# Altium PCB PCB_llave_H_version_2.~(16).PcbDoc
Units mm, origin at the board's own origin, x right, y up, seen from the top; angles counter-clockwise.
Board outline 98.1 x 71.5 mm, 2 copper layers (Top Layer, Bottom Layer); 62 components, 35 nets, 185 pads, 5 vias.
Unrouted connection lines stored in the file: 28.
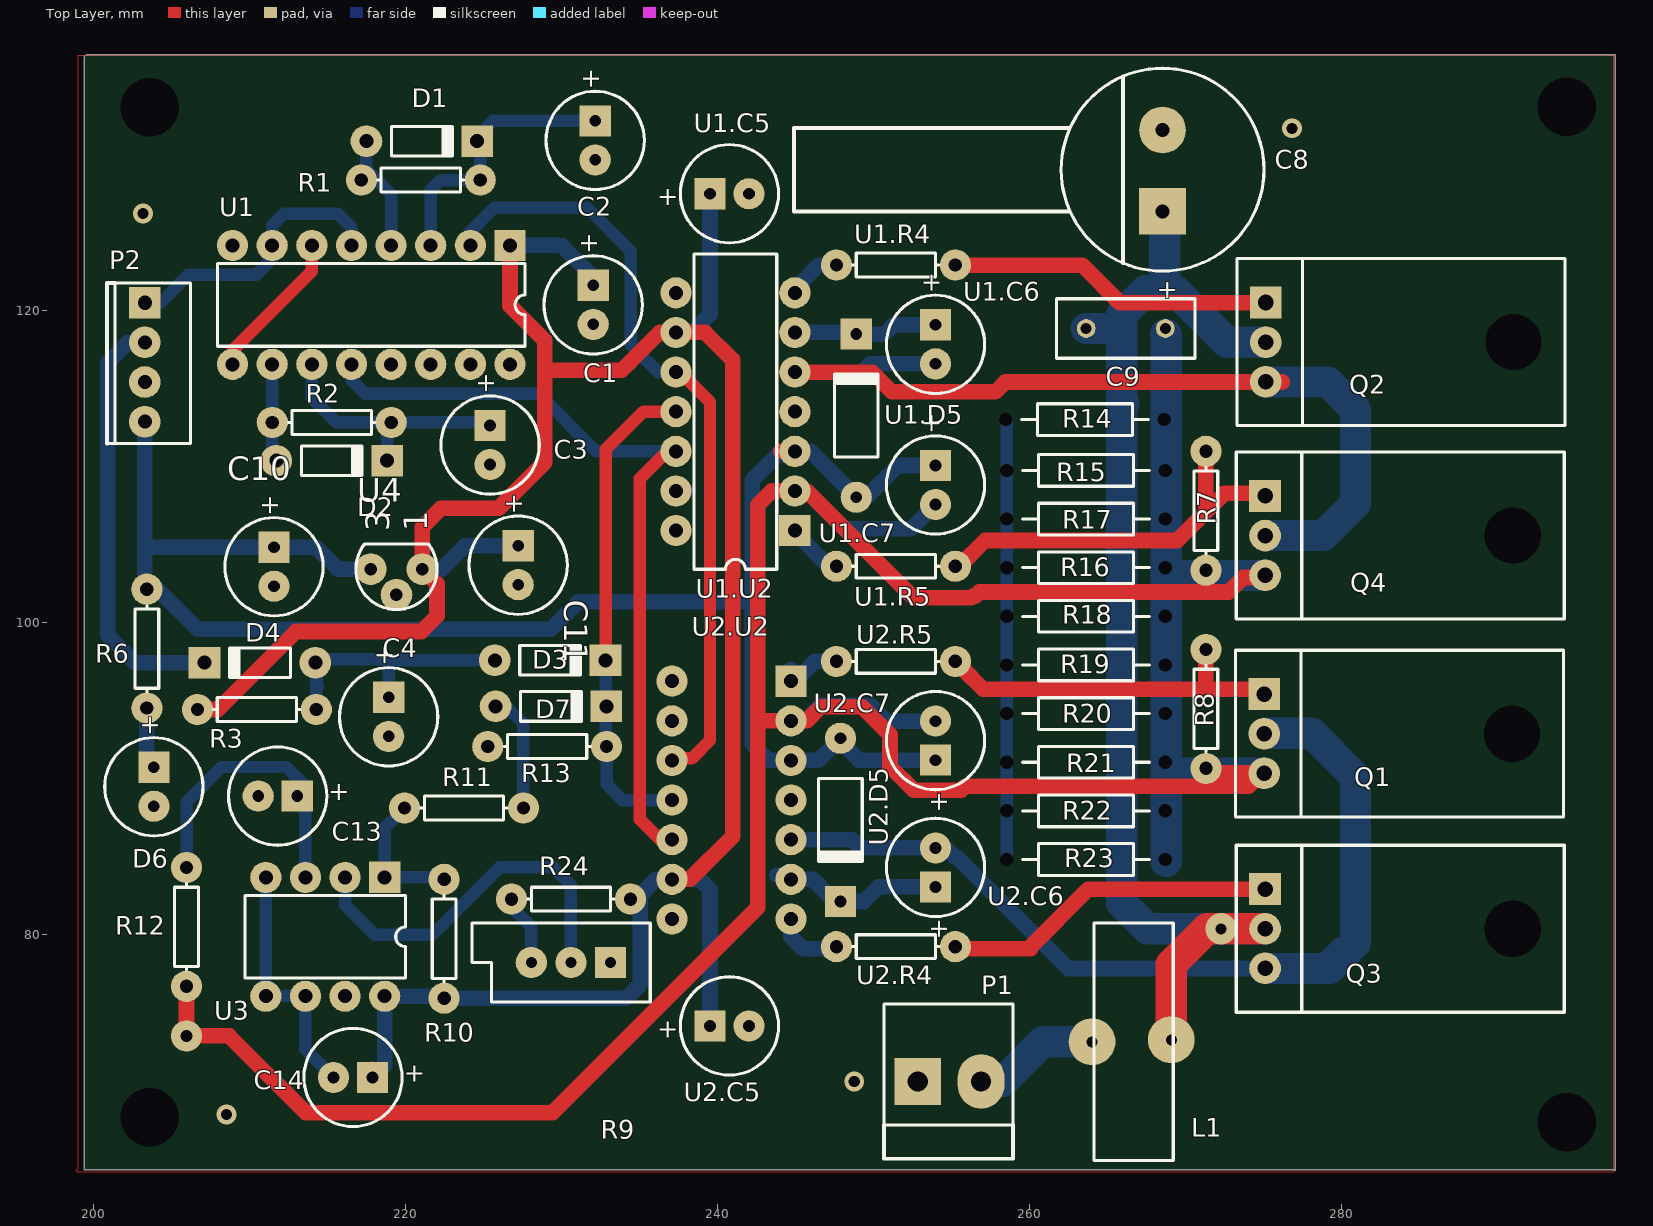
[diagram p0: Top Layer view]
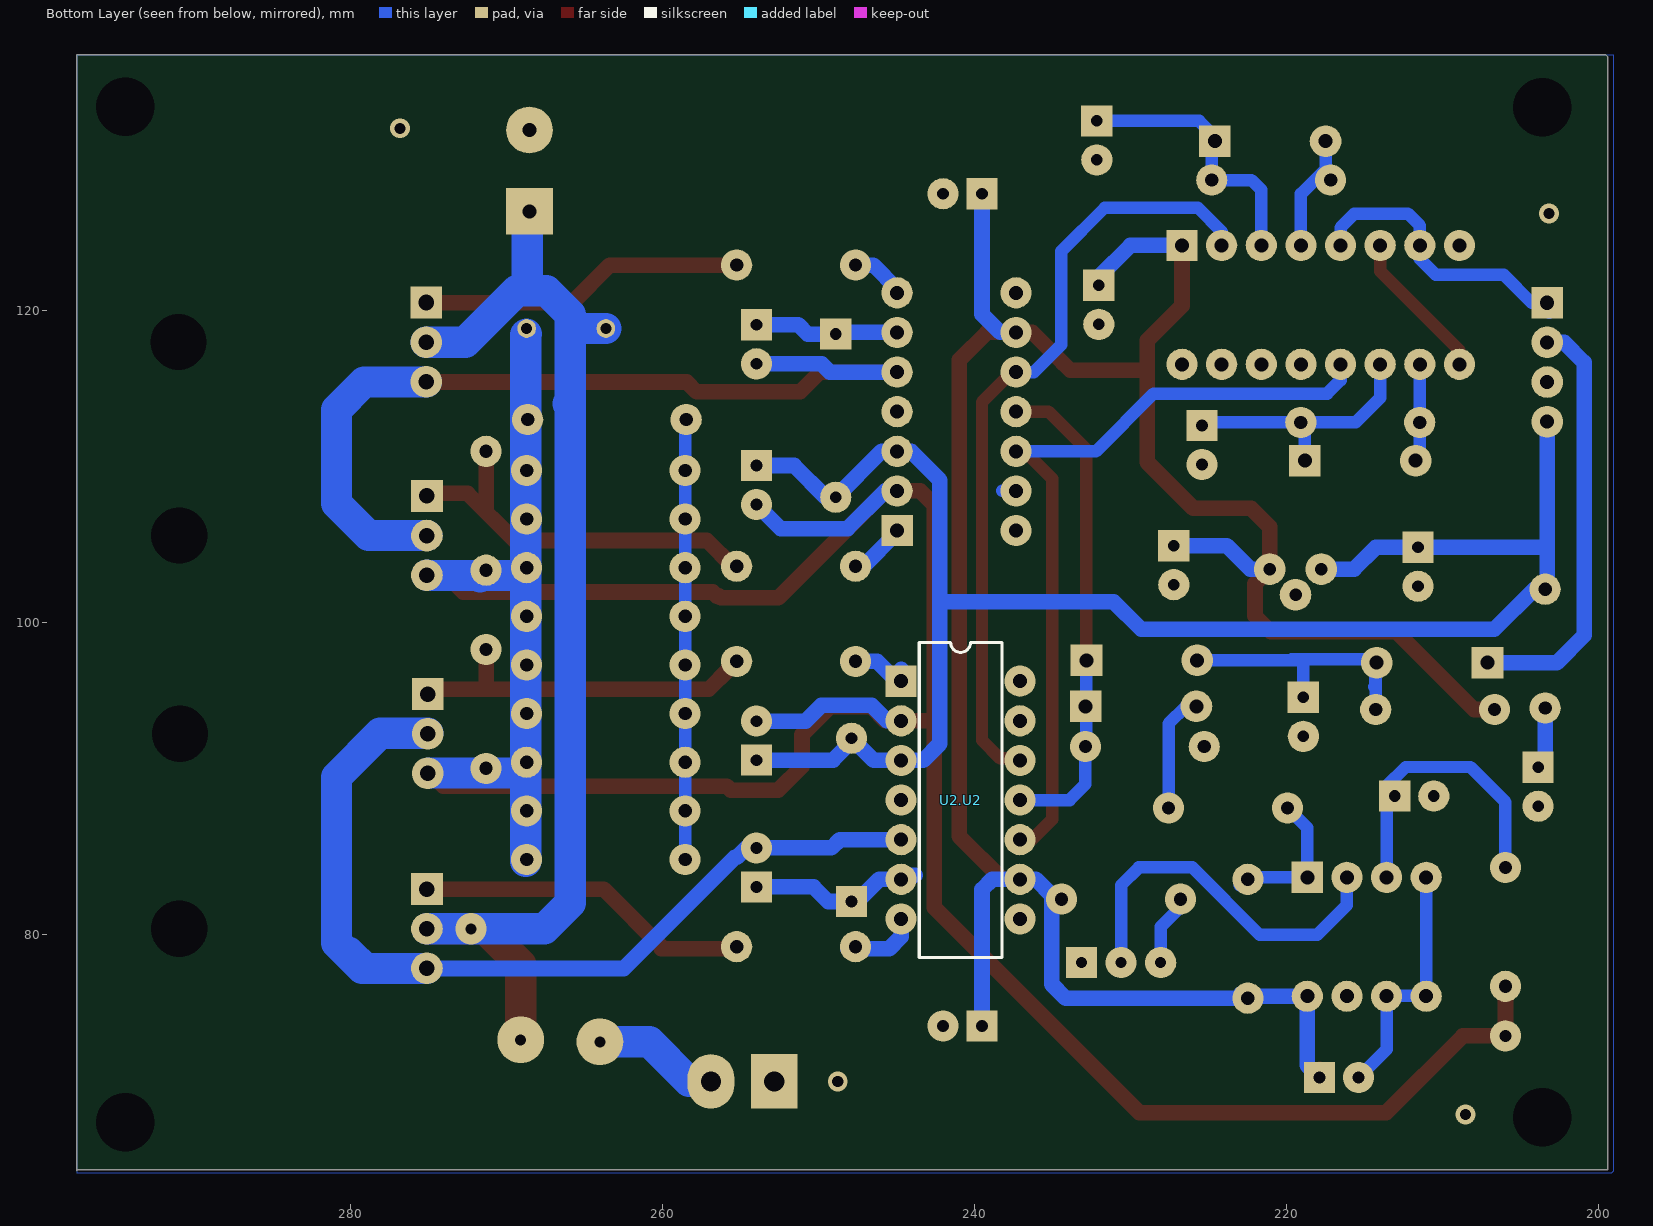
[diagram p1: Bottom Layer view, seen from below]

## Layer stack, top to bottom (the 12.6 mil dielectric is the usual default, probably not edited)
Top Layer: signal copper 0.0356
Dielectric: dielectric 0.32, FR-4, Dk 4.8
Bottom Layer: signal copper 0.0356

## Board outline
199.55,136.4 297.55,136.4 297.55,64.9 297.5,64.95 199.45,64.95 199.45,136.3

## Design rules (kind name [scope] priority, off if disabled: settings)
Clearance [All] p1: gap=0.4
ComponentClearance [All] p1: gap=0.254 collisioncheckmode=2 verticalgap=0.254
PlaneConnect [All] p1: planeconnectstyle=Direct reliefexpansion=0.508 reliefentries=4 reliefconductorwidth=0.254 reliefairgap=0.254
PolygonConnect [All] p1: connectstyle=Direct reliefconductorwidth=0.254 reliefentries=4 polygonreliefangle="90 Angle"
RoomDefinition U_regulador [InComponentClass('U_regulador')] p1: confinementstyle=ConfineIn formatcopy=TRUE lockcomponents=FALSE outline 206.7,98.85 231.45,98.85 231.45,109 206.7,109
RoomDefinition U2 [InComponentClass('U2')] p2: confinementstyle=ConfineIn formatcopy=TRUE lockcomponents=FALSE outline 276.86,69.723 229.616,69.723 229.616,109.474 276.86,109.474
RoomDefinition U1 [InComponentClass('U1')] p3: confinementstyle=ConfineIn formatcopy=TRUE lockcomponents=FALSE outline 271.272,133.604 230.759,133.604 230.759,101.981 271.272,101.981
RoomDefinition U_Puente_H [InComponentClass('U_Puente_H')] p4: confinementstyle=ConfineIn formatcopy=TRUE lockcomponents=FALSE outline 297.3,136.05 297.3,64.897 244.2,64.897 244.2,136.05
RoomDefinition U_INITShutdown [InComponentClass('U_INITShutdown')] p5: confinementstyle=ConfineIn formatcopy=TRUE lockcomponents=FALSE outline 199.45,106.045 199.45,90.297 236.347,90.297 236.347,106.045
RoomDefinition U_Shutdown [InComponentClass('U_Shutdown')] p6: confinementstyle=ConfineOut formatcopy=TRUE lockcomponents=FALSE outline 201.041,103.886 202.438,103.886 202.438,100.584 201.041,100.584
RoomDefinition Llave_H_esquema [InComponentClass('Llave_H_esquema')] p7: confinementstyle=ConfineIn formatcopy=TRUE lockcomponents=FALSE outline 199.4,64.897 297.55,64.897 297.55,136.398 199.4,136.398
RoomDefinition U_4049 [InComponentClass('U_4049')] p8: confinementstyle=ConfineIn formatcopy=TRUE lockcomponents=FALSE outline 206.15,105.4 240.186,105.4 240.186,135.88 206.15,135.88
RoutingVias [All] p1: holewidth=0.711 width=1.27 viastyle="Through Hole" minholewidth=0.711 minwidth=1.27 maxholewidth=0.711 maxwidth=1.27
SolderMaskExpansion [All] p1: expansion=0.102
TestPointUsage [All] p1: valid=0 allowmultiple=FALSE
Testpoint [All] p1: side=15 testpointundercomponent=TRUE minsize=1.016 maxsize=2.54 preferedsize=1.524 minholesize=0 maxholesize=1.016 preferedholesize=0.813 testpointgrid=0.025 style=1023 order=0123456789
Width [All] p1: maxlimit=3 minlimit=0.8 preferedwidth=1
17 further rules are at their usual default settings.

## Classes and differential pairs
component class Llave_H_esquema: D6 P1 P2 R6
component class U_4049: C1 C2 C3 D1 D2 R1 R2 U1
component class U_Puente_H: C8 C9 L1 Q1 Q2 Q3 Q4 R7 R8
component class U_Shutdown: C13 C14 D7 R9 R10 R11 R12 R13 R14 R15 R16 R17 R18 R19 R20 R21 R22 R23 R24 U3
channel class IR2110: U1 U2
component class U_INITShutdown: C4 D3 D4 R3
component class U1: U1.C5 U1.C6 U1.C7 U1.D5 U1.R4 U1.R5 U1.U2 U_1_C5 U_1_C6 U_1_C7 U_1_D5 U_1_R4 U_1_R5 U_1_U2
component class U2: D5 U2.C5 U2.C6 U2.C7 U2.D5 U2.R4 U2.R5 U2.U2 U_2.D5 U_2_C5 U_2_C6 U_2_C7 U_2_R4 U_2_R5 U_2_U2
component class U_regulador: C10 C11 U4

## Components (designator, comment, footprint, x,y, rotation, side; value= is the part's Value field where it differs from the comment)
C1 "Cap Pol1 0.1u" CAPPR2.5-6.3X5 232.058,120.386 r270 top
C2 "Cap Pol1" CAPPR2.5-6.3X5 232.185,130.927 r270 top
C3 "Cap Pol1" CAPPR2.5-6.3X5 225.45,111.4 r270 top
C4 "Cap Pol1 4.7u" CAPPR2.5-6.3X5 218.948,93.98 r270 top
C8 "Cap Pol1" CAPPR5-13X16 268.55,129.05 r0 top
C9 "Cap" RAD-0.2 266.192,118.872 r180 top
C10 "Cap Pol1 0.1u" CAPPR2.5-6.3X5 211.6,103.6 r270 top
C11 "Cap Pol1 0.1u" CAPPR2.5-6.3X5 227.25,103.7 r270 top
C13 "Cap Pol1 4.7u" CAPPR2.5-6.3X5 211.836,88.9 r180 top
C14 "Cap Pol1 0.1u" CAPPR2.5-6.3X5 216.662,70.866 r180 top
D1 "Diode1" DO-35 221.075,130.877 r0 top
D2 "Diode1" DO-35 215.3,110.4 r0 top
D3 "Diode1" DO-35 229.3,97.6 r0 top
D4 "Diode1" DO-35 210.7,97.45 r180 top
D6 "LED0" CAPPR2.5-6.3X5 203.9,89.5 r270 top
D7 "Diode1" DO-35 229.35,94.65 r0 top
L1 "Inductor" BOBINA_CHOQUE 264.16,75.692 r270 top
P1 "Header 2" PWHEADER1X2 255.016,70.612 r0 top
P2 "Header 4" HDR1X5 195.7,112.9 r270 top
Q1 "IRF3205" TO_220_H 284.9,82.05 r270 top
Q2 "IRF3205" TO_220_H 284.95,119.65 r270 top
Q3 "IRF3205" TO_220_H 284.85,94.55 r270 top
Q4 "IRF3205" TO_220_H 284.9,107.25 r270 top
R1 "18k" AXIAL-0.3 221.009,128.387 r180 top
R2 "18k" AXIAL-0.3 215.3,112.85 r0 top
R3 "4.7k" AXIAL-0.3 210.5,94.45 r180 top
R6 "1.2k" AXIAL-0.3 203.45,98.35 r90 top
R7 "6.8" AXIAL-0.3 271.33,107.188 r90 top
R8 "6.8" AXIAL-0.3 271.33,94.488 r90 top
R9 "RPot" VR5 230.632,78.232 r180 top
R10 "3.3k" AXIAL-0.3 222.504,79.756 r270 top
R11 "470" AXIAL-0.3 223.774,88.138 r0 top
R12 "6.8" AXIAL-0.3 205.994,80.518 r90 top locked
R13 "10k" AXIAL-0.3 229.108,92.075 r0 top
R14 "Res2" AXIAL-0.4 263.585,113.03 r0 top
R15 "Res2" AXIAL-0.4 263.652,109.774 r0 top
R16 "Res2" AXIAL-0.4 263.652,106.657 r0 top
R17 "Res2" AXIAL-0.4 263.652,103.539 r0 top
R18 "Res2" AXIAL-0.4 263.652,100.422 r0 top
R19 "Res2" AXIAL-0.4 263.652,97.305 r0 top
R20 "Res2" AXIAL-0.4 263.652,94.188 r0 top
R21 "Res2" AXIAL-0.4 263.652,91.07 r0 top
R22 "Res2" AXIAL-0.4 263.652,87.953 r0 top
R23 "Res2" AXIAL-0.4 263.652,84.836 r0 top
R24 "6.8" AXIAL-0.3 230.632,82.296 r0 top
U1 "MC54HC4049J" 620-09 217.834,120.386 r180 top
U1.C5 "Cap Pol1 4.7u" CAPPR2.5-6.3X5 240.792,127.508 r0 top (schematic designator C5)
U1.C6 "Cap Pol1" CAPPR2.5-6.3X5 254,117.856 r270 top (schematic designator C6)
U1.C7 "Cap Pol1" CAPPR2.5-6.3X5 254,108.839 r270 top (schematic designator C7)
U1.D5 "Diode" DO-204AL 248.92,113.284 r90 top (schematic designator D5)
U1.R4 "10" AXIAL-0.3 251.46,122.936 r0 top (schematic designator R4)
U1.R5 "10" AXIAL-0.3 251.46,103.632 r0 top (schematic designator R5)
U1.U2 "IR2110" PDIP14 241.173,113.538 r90 top (schematic designator U2)
U2.C5 "Cap Pol1 4.7u" CAPPR2.5-6.3X5 240.792,74.168 r0 top (schematic designator C5)
U2.C6 "Cap Pol1" CAPPR2.5-6.3X5 254,84.328 r90 top (schematic designator C6)
U2.C7 "Cap Pol1" CAPPR2.5-6.3X5 254,92.456 r90 top (schematic designator C7)
U2.D5 "Diode" DO-204AL 247.904,87.376 r270 top (schematic designator D5)
U2.R4 "10" AXIAL-0.3 251.46,79.248 r0 top (schematic designator R4)
U2.R5 "10" AXIAL-0.3 251.46,97.536 r0 top (schematic designator R5)
U2.U2 "IR2110" PDIP14 240.919,88.646 r270 bottom (schematic designator U2)
U3 "LM393N" 626-05 214.884,79.883 r180 top
U4 "µA78L05ACLP" LP03 219.45,103.45 r90 top

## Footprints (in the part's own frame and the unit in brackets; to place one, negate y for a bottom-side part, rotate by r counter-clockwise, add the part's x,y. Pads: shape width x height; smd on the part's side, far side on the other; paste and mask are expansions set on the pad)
620-09 [mm] "DIP; 16 Leads; Row Spacing 7.62 mm; Pitch 2.54 mm"
  rect 2x2 hole 0.9: 1(-8.89,-3.81)
  round 2 hole 0.9: 2(-6.35,-3.81) 3(-3.81,-3.81) 4(-1.27,-3.81) 5(1.27,-3.81) 6(3.81,-3.81) 7(6.35,-3.81) 8(8.89,-3.81) 9(8.89,3.81) 10(6.35,3.81) 11(3.81,3.81) 12(1.27,3.81) 13(-1.27,3.81) 14(-3.81,3.81) 15(-6.35,3.81) 16(-8.89,3.81)
  silkscreen extent -9.85,-2.65 9.85,2.65
626-05 [mm] "DIP; 8 Leads; Row Spacing 7.62 mm; Pitch 2.54 mm"
  rect 2x2 hole 0.9: 1(-3.81,-3.81)
  round 2 hole 0.9: 2(-1.27,-3.81) 3(1.27,-3.81) 4(3.81,-3.81) 5(3.81,3.81) 6(1.27,3.81) 7(-1.27,3.81) 8(-3.81,3.81)
  silkscreen extent -5.15,-2.65 5.15,2.65
AXIAL-0.3 [mm] "Resistor; 2 Leads"
  round 2 hole 0.85: 1(-3.81,0) 2(3.81,0)
  silkscreen extent -2.77,-0.76 2.77,0.76
AXIAL-0.4 [mm] "Resistor; 2 Leads"
  round 0 / inner round 0 / far side round 2 hole 0.85: 1(-5.08,0) 2(5.08,0)
  silkscreen extent -4.06,-1.02 4.06,1.02
BOBINA_CHOQUE [mm]
  round 3 hole 0.7: 1(2.54,-0.127) 2(2.413,4.953)
  silkscreen extent -5.08,0 10.16,5.08
CAPPR2.5-6.3X5 [mm] "Capacitor, Electrolytic, Radial; Body 6.3 x 5 mm (Dia.xH typ); Pin Spacing 2.5 mm (typ)"
  rect 2x2 hole 0.75: 1(-1.25,0)
  round 2 hole 0.75: 2(1.25,0)
  silkscreen extent -3.15,-3.15 3.15,3.15
CAPPR5-13X16 [mm] "Capacitor, Electrolytic, Radial; Body 13 x 16 mm (Dia.xH typ); Pin Spacing 5 mm (typ)"
  rect 3x3 hole 0.9: 1(0,-2.667)
  round 3 hole 0.9: 2(0,2.54)
  silkscreen extent -23.62,-6.5 6.5,6.5
DO-35 [mm] "Diode, Axial; Body 3.8 x 1.9 mm (LxDia. max), Lead Dia. 0.53 mm (max)"
  round 2.032 hole 0.9: 1(-3.55,0)
  rect 2.032x2.032 hole 0.9: 2(3.55,0)
  silkscreen extent -1.95,-0.95 2.05,0.95
DO-204AL [mm] "Diode, Axial; Body 5.2 x 2.7 mm (LxDia. max), Lead Dia. 0.86 mm (max)"
  round 2 hole 0.75: 1(-5.23,0)
  rect 2x2 hole 0.75: 2(5.23,0)
  silkscreen extent -2.65,-1.41 2.75,1.4
HDR1X5 [mil]
  rect 80x80 hole 35.43: 1(-300,300)
  round 80 / inner round 0 / far side round 80 hole 35.43: 2(-200,300) 3(-100,300) 4(0,300)
  silkscreen extent -350,205 55,415
LP03 [mil] "TO, Flat Index; 3 In-Line, Axial Leads; Body Dia. 4.8mm; Leads 0.56 x 0.41 mm (max)"
  round 80 hole 31.5: 1(0,-65) 2(-65,0) 3(0,65)
  silkscreen extent -102,-102 63,102
PDIP14 [mm] "DIP; 14 Leads; Row Spacing 7.62 mm; Pitch 2.54 mm"
  rect 2x2 hole 0.9: 1(-7.62,-3.81)
  round 2 hole 0.9: 2(-5.08,-3.81) 3(-2.54,-3.81) 4(0,-3.81) 5(2.54,-3.81) 6(5.08,-3.81) 7(7.62,-3.81) 8(7.62,3.81) 9(5.08,3.81) 10(2.54,3.81) 11(0,3.81) 12(-2.54,3.81) 13(-5.08,3.81) 14(-7.62,3.81)
  silkscreen extent -10.1,-2.65 10.1,2.65
PWHEADER1X2 [mm]
  rect 3x3 / inner round 0 / far side rect 3x3.5 hole 1.3: 1(-2.159,0)
  oval 3x3.5 / inner round 0 / far side oval 3x3.5 hole 1.3: 2(1.905,0)
  silkscreen extent -4.32,-4.95 3.94,4.95
RAD-0.2 [mm] "Jumper Wire; 2 Leads"
  round 1.2 hole 0.7: 1(-2.54,0) 2(2.54,0)
  silkscreen extent -4.44,-1.91 4.44,1.91
TO_220_H [mil] "to-220 horizontal"
  rect 80x80 hole 39.37: 1(-35,-385)
  round 80 hole 39.37: 2(65,-385) 3(165,-385)
  round 80 hole 141.73: 4(65,240)
  silkscreen extent -146,-458 276,370
VR5 [mm] "Potentiometer; 3 Leads"
  rect 2x2 hole 0.7: 1(-2.54,0)
  round 2 hole 0.7: 2(2.54,0) 3(0,0)
  silkscreen extent -5.08,-2.54 6.35,2.54

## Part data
C1 C4 C10 C11 C14 U1.C5 U2.C5: library part "Cap Pol1", "Polarized Capacitor (Radial)"
C2 C3 C8 U1.C6 U1.C7 U2.C6 U2.C7: "Polarized Capacitor (Radial)"
C9: "Capacitor"
C13: library part "Cap Pol1", "Polarized 16V"
D1 D2 D3 D4 D7: library part Diode, "1N4148"
D6: "Typical INFRARED GaAs LED"
P1: "Header, 2-Pin"
P2: "Header, 4-Pin"
Q1 Q2 Q3 Q4: "HEXFET Power MOSFET"
R1 R2 R3 R6 R7 R8 R10 R11 R12 R13 R24 U1.R4 U1.R5 U2.R4 U2.R5: library part Res2, "Resistor"
R9: "Potenciomentro multivuelta"
R14 R15 R16 R17 R18 R19 R20 R21 R22 R23: "metal film 1W"
U1: "Hex Inverting Buffer/Logic-Level Down Converter"
U1.D5 U2.D5: "1N5819"
U1.U2 U2.U2: "High and Low Side Driver"
U3: "Dual Comparator"
U4: "Positive-Voltage Regulator"

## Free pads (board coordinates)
  round 1.524 hole 3.75: 0(203.65,68.3) 0(203.65,133.05) 0(294.45,68) 0(294.45,133.096)
  round 2 hole 0.762: 1(205.994,73.533)

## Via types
v1: diameter 1.27, hole 0.711, Top Layer to Bottom Layer, 4 vias
v2: diameter 2, hole 0.711, Top Layer to Bottom Layer, 1 vias

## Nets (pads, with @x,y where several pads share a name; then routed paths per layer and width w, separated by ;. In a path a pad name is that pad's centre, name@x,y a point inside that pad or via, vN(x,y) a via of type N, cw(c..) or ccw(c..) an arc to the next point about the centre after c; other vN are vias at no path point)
COMMON: C9.1 pad.1 Q3.3 Q4.3 R7.1 R8.1 R12.1 R14.2 R15.2 R16.2 R17.2 R18.2 R19.2 R20.2 R21.2 R22.2 R23.2 U1.C7.2 U1.U2.2 U2.C7.2 U2.U2.2 | length 214.8
  Top Layer w1: pad.1 208.717,73.533 213.65,68.6 229.45,68.6 242.6,81.75 242.6,107.55 243.508,108.458 U1.U2.2 ; pad.1@205.994,73.556 R12.1 ; 242.6,93.726 245.745,93.726 246.634,94.615 249.301,94.615 251.079,92.837 251.079,90.805 252.603,89.281 255.646,89.281 255.9,89.535 274.066,89.535 Q3.3@274.913,90.382 ; U1.U2.2@245.745,108.458 252.603,101.6 256.286,101.6 256.413,101.727 256.54,101.727 256.794,101.981 272.796,101.981 273.727,102.912 Q4.3@275.121,102.912 ; R8.1@271.78,90.382 Q3.3@275.071,90.382
  Bottom Layer w1: U1.U2.2 245.745,108.458 248.158,106.045 252.456,106.045 U1.C7.2 ; U2.U2.2@245.633,93.726 246.629,94.722 249.829,94.722 250.845,93.706 U2.C7.2 ; R7.1@271.713,102.997 R7.1@271.798,102.912
  Bottom Layer w2: C9.1@268.732,118.526 268.792,118.465 R23.2@268.792,84.709 ; R21.2@268.792,90.382 Q3.3@275,90.382 ; R17.2@268.792,103.031 Q4.3 ; R7.1@271.713,102.965 R7.1@271.78,103.031
GND: C1.2 C2.2 C3.2 C4.2 C8.2 C10.2 C11.2 C13.2 C14.2 D6.2 P1.1 P2.3 pad.0 R9.1 R13.1 R14.1 R15.1 R16.1 R17.1 R18.1 R19.1 R20.1 R21.1 R22.1 R23.1 U1.8 U1.C5.2 U1.U2.13 U2.C5.2 U2.U2.13 U3.4 U3.5 U3.6 U4.2 | length 45.2
  Top Layer w0.8: U3.5 211.094,76.093 U3.5@211.074,76.113 ; U3.6@213.594,76.093 U3.6
  Bottom Layer w0.8: U3.5 U3.4 ; U3.5@211.094,76.093 U3.6@213.594,76.093 ; U3.6 213.614,72.664 C14.2 ; U1.U2.13 U1.U2.13@238.252,108.458 ; R23.1 R14.1@258.572,112.963
  other v1: 208.55,68.5 248.793,70.612 203.2,126.238 276.85,131.7
HO1: Q2.1 U1.R4.2 | length 20.9
  Top Layer w1: U1.R4.2 263.398,122.936 265.811,120.523 Q2.1@275.171,120.523
HO2: Q1.1 U2.R4.2 | length 20.9
  Top Layer w1: U2.R4.2@255.905,79.121 260.096,79.121 ; 259.969,79.121 263.779,82.931 Q1.1@275.121,82.931
IN_SD: D4.2 P2.2 | length 27.3
  Bottom Layer w1: P2.2 202.23,117.98 200.95,116.7 200.95,99.2 202.7,97.45 D4.2
LO1: Q4.1 R7.2 U1.R5.2 | length 26
  Top Layer w1: U1.R5.2 255.524,103.632 257.175,105.283 269.494,105.283 272.511,108.3 274.813,108.3 Q4.1@275.121,107.992 ; 271.33,107.119 R7.2 ; R7.2@271.78,110.998 R7.2@271.78,111.252
LO2: Q3.1 R8.2 U2.R5.2 | length 23.2
  Top Layer w1: U2.R5.2@255.778,97.536 255.778,97.028 257.048,95.758 Q3.1@275,95.758 ; 271.3,95.758 271.33,95.788 R8.2 ; R8.2@271.526,98.679 R8.2@271.78,98.425
MOTOR+: Q2.3 Q4.2 U1.C6.2 U1.U2.5 | length 60.4
  Top Layer w1: U1.U2.5 249.936,116.078 251.206,114.808 257.836,114.808 258.471,115.443 276.225,115.443
  Bottom Layer w1: U1.U2.5 249.301,116.078 249.829,116.606 U1.C6.2
  Bottom Layer w2: Q4.2 278.873,105.599 280.924,107.65 280.924,113.665 279.146,115.443 Q2.3@275.171,115.443
MOTOR-: Q1.3 Q3.2 U2.C6.2 U2.U2.5 | length 62.3
  Bottom Layer w1: U2.U2.5 248.666,86.106 249.194,85.578 254.655,85.578 255.255,84.978 255.382,84.978 262.509,77.851 Q1.3@275.121,77.851
  Bottom Layer w2: Q3.2@275.071,92.922 278.13,92.922 280.924,90.128 280.924,79.502 279.273,77.851 276.225,77.851 ; Q1.3 279.109,77.859 280.15,78.9
NetC2_1: C2.1 D1.2 R1.1 U1.3 | length 18.1
  Bottom Layer w0.8: U1.3 221.644,127.752 222.279,128.387 R1.1@225.2,128.387 ; R1.1@224.825,128.387 224.825,131.377 225.625,132.177 C2.1
NetC3_1: C3.1 D2.2 R2.2 U1.11 | length 22
  Bottom Layer w0.8: U1.11 214.024,114.426 215.6,112.85 C3.1@225.25,112.85 ; D2.2@218.844,110.4 R2.2@218.844,111.977 ; R2.2 C3.1@225.25,112.85 ; C3.1 C3.1@225.25,112.85
NetC4_1: C4.1 D3.1 D4.1 R3.1 | length 20.3
  Bottom Layer w0.8: R3.1 214.31,97.66 219.69,97.66 219.75,97.6 ; D4.1@214.35,97.66 214.35,95.96 214.41,95.9 ; C4.1 218.948,97.598 ; 218.95,97.6 D3.1 D3.1@225.306,98.044
NetC13_1: C13.1 R12.2 U3.3 | length 19.1
  Bottom Layer w0.8: R12.2 205.994,88.519 208.24,90.765 212.384,90.765 213.614,89.535 U3.3
NetD1_1: D1.1 R1.2 U1.4 | length 7.3
  Bottom Layer w0.8: D1.1 217.525,129.077 219.104,127.498 U1.4
NetD2_1: D2.1 R2.1 U1.10 | length 6.3
  Bottom Layer w0.8: U1.10 211.484,110.666 D2.1
NetD6_1: D6.1 R6.1 | length 4
  Bottom Layer w1: R6.1 203.45,91.2 D6.1
NetD7_1: D7.1 R11.2 | length 7.7
  Bottom Layer w0.8: D7.1 226.484,94.65 227.584,93.55 R11.2
NetR9_2: R9.2 R24.1 | length 4.8
  Bottom Layer w0.8: R24.1@226.949,82.55 226.949,81.661 228.092,80.518 R9.2
NetR9_3: R9.3 U3.2 | length 24.3
  Bottom Layer w0.8: U3.2 216.154,81.915 218.059,80.01 221.742,80.01 226.06,84.328 229.489,84.328 230.632,83.185 R9.3
NetR10_1: R10.1 R11.1 U3.1 | length 9.5
  Bottom Layer w0.8: R11.1 218.694,86.868 U3.1 222.504,83.693 R10.1@223.012,83.185
NetU1.C6_1: U1.C6.1 U1.D5.2 U1.U2.6 | length 9.8
  Bottom Layer w1: U1.U2.6 248.308,118.618 248.412,118.514 250.721,118.514 251.313,119.106 U1.C6.1 ; U1.D5.2@248.943,118.872 U1.D5.2@249.301,118.514
NetU1.R4_1: U1.R4.1 U1.U2.7 | length 3.8
  Bottom Layer w1: U1.U2.7 244.983,121.412 246.507,122.936 U1.R4.1@247.904,122.936
NetU1.R5_1: U1.R5.1 U1.U2.1 | length 3.7
  Bottom Layer w1: U1.U2.1 244.983,105.791 247.142,103.632 U1.R5.1
NetU1_6: U1.6 U1.9 | length 9.9
  Top Layer w0.8: U1.9 208.944,117.465 214.024,122.545 U1.6
  Bottom Layer w0.8: U1.9 U1.9@208.944,116.703
NetU2.C6_1: U2.C6.1 U2.D5.2 U2.U2.6 | length 10.8
  Bottom Layer w1: U2.U2.6@243.84,83.82 U2.U2.6@244.602,83.82 ; U2.U2.6 246.126,83.566 U2.D5.2@247.673,82.019 ; U2.D5.2 249.405,82.146 250.337,83.078 U2.C6.1
NetU2.R4_1: U2.R4.1 U2.U2.7 | length 4.9
  Bottom Layer w1: U2.U2.7 244.729,79.883 245.491,79.121 U2.R4.1@248.158,79.121
NetU2.R5_1: U2.R5.1 U2.U2.1 | length 4.7
  Bottom Layer w1: U2.U2.1@244.729,97.028 U2.U2.1 244.983,96.266 246.253,97.536 U2.R5.1@248.158,97.536
PWM: P2.1 U1.5 U1.7 | length 18.9
  Bottom Layer w0.8: P2.1@203.2,119.888 P2.1@203.576,120.264 ; P2.1 204.319,120.52 206.1,122.301 210.45,122.301 211.484,123.335 211.484,125.466 212.246,126.228 215.675,126.228 216.564,125.339 U1.5
SD: D3.2 D7.2 R13.2 U1.U2.11 U2.U2.11 | length 31.6
  Top Layer w0.8: D3.2 232.85,111.1 235.288,113.538 U1.U2.11
  Bottom Layer w0.8: D3.2 232.85,92.068 232.918,92 232.918,89.662 233.934,88.646 U2.U2.11
U1.HIN: U1.2 U1.U2.10 U2.U2.12 | length 50
  Top Layer w0.8: U2.U2.12@237.236,91.313 238.379,91.313 239.545,92.479 239.545,114.155 237.622,116.078 U1.U2.10
  Bottom Layer w0.8: U1.2 224.184,125.085 225.708,126.609 231.677,126.609 234.471,123.815 234.471,117.827 236.22,116.078 U1.U2.10
U1.LIN: U1.12 U1.U2.12 U2.U2.10 | length 51.2
  Top Layer w0.8: U2.U2.10 236.344,86.106 235.05,87.4 235.05,109.25 236.798,110.998 U1.U2.12
  Bottom Layer w0.8: U1.12 216.564,115.56 217.424,114.7 228.55,114.7 232.252,110.998 U1.U2.12
VCC: C10.1 P2.4 R6.2 U1.C7.1 U1.D5.1 U1.U2.3 U2.C7.1 U2.D5.1 U2.U2.3 U4.3 | length 112.3
  Top Layer w1: U1.U2.3@244.098,110.998 U1.U2.3
  Bottom Layer w1: 203.32,104.75 203.42,104.85 214.3,104.85 215.7,103.45 U4.3 ; P2.4 203.32,102.29 R6.2 204.14,102.16 206.7,99.6 229.35,99.6 231.1,101.35 242.2,101.35 242.25,101.3 ; U2.C7.1 249.094,91.206 247.904,92.396 U2.D5.1 246.484,91.186 243.314,91.186 242.25,92.25 242.25,109.15 244.098,110.998 245.976,110.998 U1.D5.1 249.554,108.054 251.589,110.089 U1.C7.1
VCC_MOTOR: L1.1 P1.2 | length 8.2
  Bottom Layer w2: P1.2 258.318,70.612 260.858,73.152 L1.1
VCC_MOTOR_FILTRADO: C8.1 C9.2 L1.2 Q1.2 Q2.2 | length 78
  Top Layer w2: L1.2 269.113,78.105 271.399,80.391 Q1.2@275.121,80.391
  Bottom Layer w2: C9.2 265.811,118.872 265.938,118.745 ; 265.938,113.919 266.065,114.046 ; 268.692,121.579 C8.1@268.692,126.45 ; Q1.2@275.121,80.391 267.589,80.391 265.938,82.042 265.938,119.761 267.462,121.285 269.367,121.285 272.669,117.983 Q2.2@275.171,117.983
  other v2: 272.288,80.391
VDD: C1.1 C11.1 C14.1 R3.2 R10.2 R24.2 U1.1 U1.C5.1 U1.U2.9 U2.C5.1 U2.U2.9 U3.8 U4.1 | length 164
  Top Layer w0.8: C14.1 C14.1@217.912,71.481 ; U3.8@218.567,76.327 218.694,76.2 U3.8
  Top Layer w1: R3.2 208,94.45 213,99.45 221.05,99.45 222.05,100.45 222.05,102.501 U4.1 221.101,106.151 222.3,107.35 226,107.35 228.95,110.3 228.95,118.1 226.724,120.326 U1.1 ; 228.95,116.2 233.9,116.2 234.35,116.65 236.318,118.618 239.232,118.618 241,116.85 241,86.314 238.252,83.566 U2.U2.9
  Bottom Layer w0.8: R10.2@222.994,76.309 R10.2@223.012,76.292 ; C1.1 C1.1@232.058,122.037
  Bottom Layer w1: C14.1 218.694,71.648 U3.8 R10.2@222.758,76.073 ; U4.1 222.35,103.45 223.85,104.95 C11.1 ; R10.2 234.188,75.946 235.077,76.835 235.077,82.55 236.093,83.566 238.887,83.566 239.542,82.911 U2.C5.1 ; U1.1 230.026,124.196 232.058,122.164 C1.1 ; 238.379,118.618 239.542,119.781 U1.C5.1
pads on no net: Q1.4 Q2.4 Q3.4 Q4.4 U1.13 U1.14 U1.15 U1.16 U1.U2.4 U1.U2.8 U1.U2.14 U2.U2.4 U2.U2.8 U2.U2.14 U3.7

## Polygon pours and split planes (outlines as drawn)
GND on Bottom Layer "Bottom Layer-GND" (solid, remove dead copper, shelved, pour order 1001): 199.05,136.398 297.55,136.398 297.55,64.77 199.195,64.77 199.05,64.897
GND on Top Layer "Top Layer-GND" (solid, remove dead copper, shelved, pour order 1000): 199.046,136.398 297.45,136.398 297.45,64.8 199.046,64.8 198.9,64.927 199.046,65.054

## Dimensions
191.008,215.519 to 316.992,211.201 on Top Layer
258.064,52.578 to 207.391,218.567 on Top Layer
